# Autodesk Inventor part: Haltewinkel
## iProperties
Title: Haltewinkel
Created: 2006-03
Part Number: T 363 585
Material: 1.0112.00
Description: Haltewinkel
Vendor: Autodesk Inc.
Document SubType Name: Modeling
Standard: EN 10056-1
Designer: I.Baliuc
Standards Organization: DIN
Language: de-DE
Size Designation: 50 x 50 x 5 - 200
Categories: <MemberInstance Version="R10.0.0"><Categories><Category DisplayName="Profilstahle" InternalName="089c4875-fa83-4c05-b084-43b9cc11f5ed" Mnemonic="GRDR"><Category
Density: 7.84 g/cm^3
G_L: 200,000 mm
Rohabmessung: 50 x 5 - 200
Zweck: Trennerbefestigung
Author: T.Messerschmitt
Keywords: 381137
Comments: EN 10056-1 - 50 x 50 x 5 - 200 scharfkantiges L-Profil
Revision Number: 363585
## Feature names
1. Körper [Extrusion]
2. Rundung1 [Fillet]
3. Rundung2 [Fillet]
4. Bohrung1 [Hole]
5. Bohrung2 [Hole]
